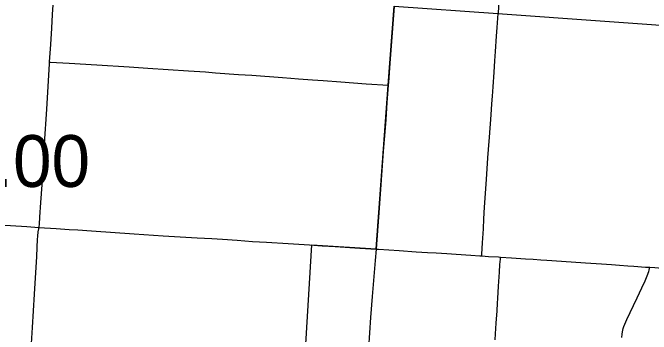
# Model space of a CAD drawing. Extents: x 9078 to 9739, y 4248 to 4966.
# Drawn here: x 9241.2 to 9309.1, y 4486.1 to 4520.2 of the extents above; entities that cross this region are included whole.
import ezdxf

# ---------------------------------------------------------------- set-up
doc = ezdxf.new("R2010")
doc.units = 0
for name, color, linetype in [('Default', 7, 'Continuous'), ('GM_X_County_Road', 7, 'Continuous'), ('GM_X_Township', 7, 'Continuous'), ('GM_X_Township_Road', 7, 'Continuous')]:
    doc.layers.add(name, color=color, linetype=linetype)

msp = doc.modelspace()

# ---------------------------------------------------------------- linework, layer by layer
at = {"layer": 'GM_X_County_Road'}
for points in [[(9292.827, 4520.15), (9292.833, 4520.223), (9292.919, 4521.451), (9293.034, 4523.09), (9293.183, 4525.301), (9293.256, 4526.284), (9293.309, 4526.938), (9293.366, 4527.757), (9293.439, 4528.986), (9293.51, 4529.969), (9293.732, 4533.163), (9293.84, 4534.719), (9293.925, 4535.947), (9293.979, 4536.765), (9294.015, 4537.277)], [(9245.138, 4515.019), (9245.257, 4516.879), (9245.367, 4518.599), (9245.465, 4520.073), (9245.662, 4523.102), (9245.699, 4523.736)], [(9281.158, 4512.54), (9281.187, 4512.836), (9281.344, 4514.883), (9281.522, 4517.176), (9281.765, 4520.452), (9281.797, 4520.915)], [(9291.06, 4494.419), (9291.071, 4494.587), (9291.154, 4495.816), (9291.238, 4497.291), (9291.304, 4498.356), (9291.374, 4499.586), (9291.566, 4502.535), (9291.727, 4504.828), (9291.79, 4505.73), (9291.885, 4507.04), (9292.054, 4509.415), (9292.141, 4510.561), (9292.203, 4511.379), (9292.269, 4512.362), (9292.379, 4513.918), (9292.463, 4515.147), (9292.538, 4516.129), (9292.648, 4517.767), (9292.716, 4518.668), (9292.827, 4520.15)], [(9244.014, 4497.443), (9244.024, 4497.502), (9244.062, 4497.798), (9244.122, 4498.533), (9244.222, 4500.089), (9244.338, 4501.973), (9244.393, 4502.956), (9244.479, 4504.266), (9244.609, 4506.313), (9244.839, 4509.999), (9245.055, 4513.603), (9245.127, 4514.832), (9245.138, 4515.019)], [(9279.878, 4495.146), (9279.955, 4496.141), (9280.224, 4499.985), (9280.292, 4500.966), (9280.635, 4505.545), (9280.795, 4507.588), (9280.894, 4508.896), (9281.024, 4510.695), (9281.158, 4512.54)], [(9242.196, 4468.658), (9242.207, 4468.816), (9242.45, 4472.582), (9242.578, 4474.547), (9242.619, 4475.284), (9242.648, 4475.857), (9242.779, 4477.821), (9242.928, 4480.114), (9243.067, 4482.325), (9243.142, 4483.471), (9243.234, 4485.109), (9243.324, 4486.83), (9243.536, 4490.352), (9243.77, 4494.366), (9243.872, 4496.249), (9243.888, 4496.438), (9243.909, 4496.66), (9243.924, 4496.85), (9243.935, 4496.978), (9243.988, 4497.293), (9244.014, 4497.443)], [(9272.778, 4495.586), (9274.112, 4495.497), (9275.497, 4495.411), (9278.106, 4495.248), (9279.878, 4495.146)], [(9277.938, 4466.43), (9278, 4467.515), (9278.129, 4469.643), (9278.395, 4473.816), (9278.503, 4475.534), (9278.734, 4479.545), (9278.953, 4482.982), (9279.287, 4487.889), (9279.465, 4490.096), (9279.785, 4493.935), (9279.878, 4495.146)], [(9279.878, 4495.146), (9280.078, 4495.133), (9282.287, 4494.989), (9284.088, 4494.867), (9285.315, 4494.791), (9286.216, 4494.736), (9287.362, 4494.669), (9288.344, 4494.608), (9289.899, 4494.501), (9290.88, 4494.431), (9291.06, 4494.419)], [(9291.06, 4494.419), (9291.78, 4494.371), (9292.845, 4494.313), (9293.059, 4494.298)], [(9292.5, 4485.49), (9292.545, 4486.144), (9292.614, 4487.29), (9292.699, 4488.599), (9292.754, 4489.417), (9292.785, 4489.907), (9292.863, 4491.217), (9292.955, 4492.689), (9293.003, 4493.507), (9293.044, 4494.079), (9293.059, 4494.298)], [(9293.059, 4494.298), (9294.236, 4494.221), (9295.708, 4494.111), (9296.526, 4494.056), (9297.344, 4494.003), (9297.999, 4493.965), (9299.554, 4493.87), (9302.091, 4493.696), (9303.236, 4493.615), (9303.809, 4493.576), (9304.873, 4493.5), (9305.691, 4493.439), (9306.589, 4493.371), (9307.244, 4493.331), (9308.471, 4493.238), (9308.935, 4493.209)], [(9308.935, 4493.209), (9309.452, 4493.176), (9309.861, 4493.149), (9310.598, 4493.095), (9311.497, 4493.033), (9312.397, 4492.968), (9313.223, 4492.911)]]:
    msp.add_lwpolyline(points, dxfattribs=at)
at = {"layer": 'GM_X_Township'}
msp.add_lwpolyline([(9268.699, 4425.694), (9269.561, 4439.455), (9271.281, 4466.878), (9273.006, 4495.59), (9279.838, 4495.183), (9281.137, 4512.561), (9281.77, 4520.946), (9292.78, 4520.165), (9315.037, 4518.585), (9316.326, 4535.676), (9316.532, 4538.568), (9316.875, 4542.9), (9317.028, 4544.828), (9317.718, 4551.986), (9321.229, 4552.295), (9324.029, 4552.602), (9334.675, 4553.48), (9360.11, 4556.507), (9359.515, 4548.555), (9366.319, 4547.914), (9372.855, 4547.273), (9397.659, 4545.2), (9410.412, 4544.235)], dxfattribs=at)
at = {"layer": 'GM_X_Township_Road'}
for points in [[(9245.138, 4515.019), (9245.217, 4515.013), (9247.231, 4514.892), (9250.178, 4514.7), (9253.616, 4514.483), (9255.581, 4514.365), (9259.916, 4514.074), (9261.711, 4513.952), (9262.773, 4513.88), (9265.227, 4513.702), (9266.618, 4513.606), (9269.887, 4513.362), (9270.785, 4513.289), (9271.602, 4513.227), (9273.073, 4513.125), (9274.214, 4513.046), (9276.096, 4512.914), (9278.794, 4512.702), (9281.158, 4512.54)], [(9225.328, 4498.616), (9225.733, 4498.605), (9226.274, 4498.567), (9227.01, 4498.51), (9228.402, 4498.427), (9230.122, 4498.323), (9232.005, 4498.208), (9235.117, 4498.012), (9237.492, 4497.86), (9239.785, 4497.721), (9242.733, 4497.529), (9244.014, 4497.443)], [(9244.014, 4497.443), (9245.844, 4497.319), (9247.236, 4497.232), (9248.137, 4497.175), (9249.61, 4497.068), (9254.113, 4496.768), (9257.224, 4496.563), (9260.828, 4496.345), (9262.384, 4496.252), (9263.53, 4496.183), (9265.086, 4496.081), (9266.722, 4495.965), (9268.197, 4495.881), (9270.49, 4495.733), (9272.778, 4495.586)], [(9305.96, 4485.753), (9305.985, 4486.117), (9306.017, 4486.357), (9306.049, 4486.524), (9306.091, 4486.701), (9306.169, 4486.934), (9306.502, 4487.681), (9307.208, 4489.163), (9307.596, 4489.979), (9308.086, 4491.018), (9308.433, 4491.761), (9308.654, 4492.289), (9308.816, 4492.753), (9308.859, 4492.898), (9308.901, 4493.07), (9308.935, 4493.209)]]:
    msp.add_lwpolyline(points, dxfattribs=at)

# ---------------------------------------------------------------- texts
at = {"layer": 'Default'}
msp.add_text('4.00', height=5.5, dxfattribs=at).set_placement((9235.126, 4501.745))

doc.saveas('drawing.dxf')
